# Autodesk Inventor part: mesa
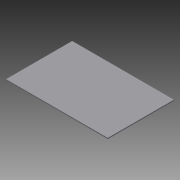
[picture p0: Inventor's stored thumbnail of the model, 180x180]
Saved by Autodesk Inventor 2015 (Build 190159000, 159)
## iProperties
Created: 2016-05
Part Number: mesa
Material: Genérico
Document SubType Name: Modeling
Designer: ALEX
Density: 1 g/cm^3
Appearance: Valor por defecto
Author: ALEX
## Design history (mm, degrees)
sketch "Boceto1"
  geometry: L1 (500, -325)-(-500, -325); L2 (-500, -325)-(-500, 325); L3 (-500, 325)-(500, 325); L4 (500, 325)-(500, -325); L5 (500, -325)-(-500, 325); L6 (-500, -325)-(500, 325); 1 further point
  constraints: 12 end point, 2 midpoint, 2 parallel, 1 horizontal, 1 perpendicular
  dimensions: "d0" = 1000 distance of L2.end L3.end; "d1" = 650 distance of L1.end L2.end
extrude "Extrusión1" new body sketch "Boceto1" distance "d2" = 10; taper "d3" = 0 deg
sketch "Boceto2"
  geometry: L1 (500, -325)-(500, 325) reference; L2 (-500, 325)-(500, 325); L3 (500, 325)-(500, 285); L4 (710, 460)-(-710, 460); L5 (-500, 285)-(-500, 325); L6 (500, 325)-(-500, 325) reference; L7 (500, -325)-(960, -325); L8 (710, -460)-(710, 460); L9 (460, 325)-(500, 325); L10 (500, 325)-(500, -325); L11 (-500, -325)-(500, -325); L12 (500, -325)-(500, -285); L13 (710, -460)-(-710, -460); L14 (-500, -635)-(-500, -325); L15 (-500, -325)-(500, -325) reference; L16 (-500, 325)-(-960, 325); L17 (-710, 460)-(-710, -460); L18 (-460, -325)-(-500, -325); L19 (-500, -325)-(-500, 325); 1 further point
  constraints: 32 end point, 8 parallel, 5 point on line, 4 horizontal, 4 perpendicular
  dimensions: "d4" = 40 distance of L2.end L3.end; "d5" = 40 distance of L9.start L9.end; "d6" = 40 distance of L12.end L11.end; "d7" = 40 distance of L18.start L18.end
extrude "Extrusión2" join sketch "Boceto2" distance "d8" = 150; taper "d9" = 0 deg
node "Boceto3"
node "Sólido1"
